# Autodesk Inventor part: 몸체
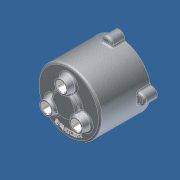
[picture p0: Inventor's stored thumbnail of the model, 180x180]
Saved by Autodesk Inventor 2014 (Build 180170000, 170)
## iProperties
Created: 2012-05
Part Number: 몸체
Document SubType Name: 모델링
Designer: SeoGD™
Material: 알루미늄 6061
Density: 1 g/cm^3
Appearance: 알루미늄 - 평지
변환 표준: STEP AP214IS
파일 이름: C:\Users\SeoGD\Desktop\?쒗뿕\紐몄껜.stp
전처리기: Build: 253, Release: 2010 SP1 - Date: Wed 07/29/2009
전송 단위: 밀리미터
불확실성: 0.01
Author: SeoGD™
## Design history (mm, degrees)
sketch "스케치2"
  geometry: C1 r 50 at (0, 0); 1 further point
  constraints: 1 centre point, 1 coincident
  dimensions: "d9" = 100 diameter of C1
extrude "돌출2" new body sketch "스케치2" distance "d10" = 80; taper "d11" = 0 deg
feature "쉘1" dims "d12" = 5
sketch "스케치3" dims "d13" = 55
  geometry: C1 r 7.5 at (0, 27.5); C2 r 12.5 at (0, 27.5); 2 further points
  constraints: 2 centre point, 2 coincident, 2 vertical alignment, 2 other
  dimensions: "d14" = 15 diameter of C1; "d15" = 25 diameter of C2
extrude "돌출3" join sketch "스케치3" distance "d16" = 12; taper "d17" = -10 deg
hole "구멍2" diameter "d20" = 15; stored, may be unused: countersink angle "d24" = 90 deg, drill point angle "d26" = 118 deg; dims "d18" = 10, "d19" = 10, "d21" = 6, "d22" = 4, "d23" = 2, "d25" = 15
chamfer "모따기1" distance "d27" = 1; stored, may be unused: second distance "d28" = 2, angle "d29" = 45 deg
sketch "스케치4"
  geometry: L1 (0, 0)-(0, 88); L2 (0, 70)-(13.16, 70); L3 (-45, 75)-(45, 75) reference; L4 (-50, 80)-(50, 80) reference; L5 (13.16, 70)-(14.5, 75); L6 (20, 80)-(20, 88); L7 (20, 88)-(0, 88); L8 (20, 80)-(14.5, 75)
  constraints: 12 end point, 3 point on line, 2 perpendicular, 1 vertical
  dimensions: "d34" = 40 diameter of L6 L1; "d35" = 105 deg angle of L5 L3; "d36" = 5 distance between parallel lines of L2 L3; "d37" = 8 distance between parallel lines of L7 L4; "d51" = 29 diameter of L5.end L1
revolve "회전1" sketch "스케치4" stored, may be unused: angle "d38" = 90 deg
hole "구멍3" diameter "d41" = 15; stored, may be unused: countersink angle "d45" = 90 deg, drill point angle "d47" = 0 deg; dims "d39" = 10, "d40" = 10, "d42" = 6, "d43" = 22, "d44" = 13, "d46" = 15
chamfer "모따기2" distance "d48" = 1; stored, may be unused: second distance "d49" = 2, angle "d50" = 45 deg
fillet "모깎기1" dims "d52" = 3
fillet "모깎기2" dims "d53" = 3, "d72" = 0.2
sketch "스케치5"
  geometry: A1 r 50 centre (0, 0) between (50, 0) and (-8.074, 49.344) reference; A2 r 8.5 centre (0, 52) between (8.074, 49.344) and (-8.074, 49.344); 1 further point
  constraints: 5 point on circle, 1 centre point, 1 horizontal alignment
  dimensions: "d54" = 90 deg dimension on point (0, 0) A2.centre A1.start; "d55" = 52 distance of A2.centre point (0, 0); "d56" = 17 diameter of A2
extrude "돌출4" join sketch "스케치5" distance "d57" = 20; taper "d58" = 0 deg
fillet "모깎기3" dims "d59" = 3
hole "구멍4" diameter "d62" = 4.134; stored, may be unused: countersink angle "d66" = 90 deg, drill point angle "d68" = 118 deg; dims "d60" = 10, "d61" = 10, "d63" = 12, "d64" = 22, "d65" = 13, "d67" = 15
sketch "스케치6"
  geometry: C1 r 47 at (0, 0) reference; C2 r 42.5 at (0, 0); 1 further point
  constraints: 1 centre point, 1 coincident, 1 other
  dimensions: "d73" = 85 diameter of C2
feature "엠보싱1" sketch "스케치6" dims "d74" = 1, "d75" = 0
node "솔리드1"
node "솔리드 본체"
node "곡면 본체"
pattern_circular "원형 패턴1" dims "d31" = 360 deg
pattern_circular "원형 패턴2" dims "d70" = 360 deg
node "솔리드2"
